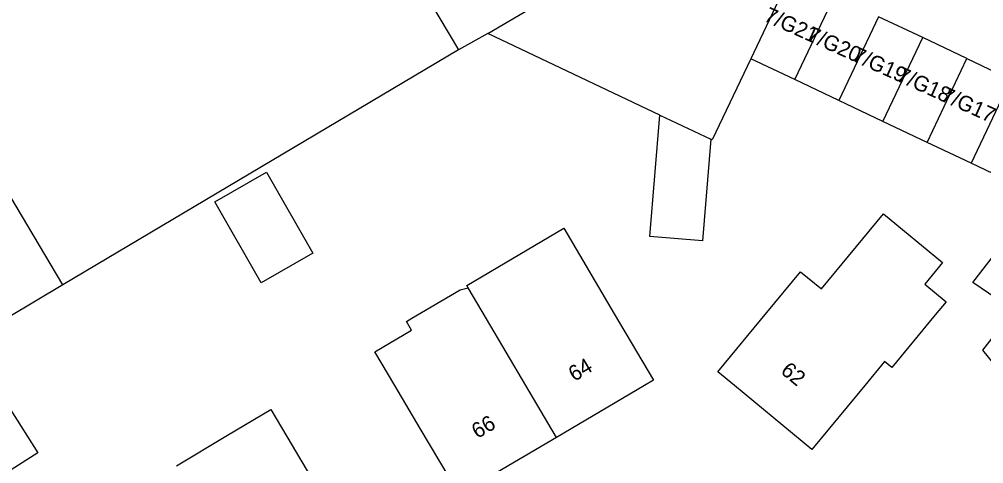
# Model space of a CAD drawing. Extents: x 159503 to 160347, y 382525 to 383272.
# Drawn here: x 159688.9 to 159751.6, y 382994.9 to 383023.8 of the extents above; entities that cross this region are included whole.
import ezdxf

# ---------------------------------------------------------------- set-up
doc = ezdxf.new("R2010")
doc.units = 0
doc.layers.add('IMGEO_Pand', color=7, linetype='Continuous')
doc.layers.add('IMGEO_Pand_nummerreeks', color=7, linetype='Continuous')

msp = doc.modelspace()

# ---------------------------------------------------------------- linework, layer by layer
at = {"layer": 'IMGEO_Pand'}
for points in [[(159707.235, 383039.014), (159717.447, 383021.814)], [(159719.37, 383022.877), (159727.798, 383027.878)], [(159739.021, 383026.698), (159736.443, 383021.244)], [(159739.304, 383019.887), (159741.889, 383025.338)], [(159691.726, 383006.538), (159681.512, 383023.741)], [(159744.757, 383023.978), (159742.172, 383018.527)], [(159747.624, 383022.618), (159744.757, 383023.978)], [(159719.37, 383022.877), (159717.447, 383021.814)], [(159730.549, 383017.575), (159719.37, 383022.877)], [(159745.039, 383017.167), (159747.624, 383022.618)], [(159750.492, 383021.257), (159747.624, 383022.618)], [(159717.447, 383021.814), (159691.726, 383006.538)], [(159736.443, 383021.244), (159733.94, 383015.967), (159733.862, 383016.004)], [(159739.304, 383019.887), (159736.443, 383021.244)], [(159747.907, 383015.807), (159750.492, 383021.257)], [(159750.492, 383021.257), (159753.36, 383019.897)], [(159742.172, 383018.527), (159739.304, 383019.887)], [(159753.36, 383019.897), (159750.775, 383014.446)], [(159745.039, 383017.167), (159742.172, 383018.527)], [(159733.862, 383016.004), (159733.304, 383009.403), (159729.882, 383009.693), (159730.549, 383017.575)], [(159730.549, 383017.575), (159733.862, 383016.004)], [(159747.907, 383015.807), (159745.039, 383017.167)], [(159750.775, 383014.446), (159747.907, 383015.807)], [(159753.643, 383013.086), (159750.775, 383014.446)], [(159707.992, 383008.609), (159704.632, 383006.683), (159701.62, 383011.936), (159704.98, 383013.863), (159707.992, 383008.609)], [(159758.283, 383010.865), (159753.467, 383004.946), (159750.876, 383006.697), (159755.183, 383012.265), (159758.283, 383010.865)], [(159748.919, 383007.996), (159747.755, 383006.585), (159749.142, 383005.441), (159748.44, 383004.59), (159745.617, 383001.169), (159745.143, 383001.56), (159743.853, 383000), (159740.42, 382995.85), (159735.39, 383000), (159734.311, 383000.89), (159737.493, 383004.747), (159739.679, 383007.397), (159741.037, 383006.277), (159745.073, 383011.167), (159748.919, 383007.996)], [(159718.079, 383006.352), (159717.995, 383006.494), (159721.45, 383008.543), (159724.297, 383010.231), (159727.581, 383004.651), (159730.118, 383000.341), (159729.54, 383000), (159723.819, 382996.623)], [(159691.726, 383006.538), (159684.709, 383002.371)], [(159723.819, 382996.623), (159717.522, 382992.906), (159714.972, 382997.208), (159713.315, 383000), (159712.015, 383002.191), (159714.397, 383003.603), (159714.066, 383004.161), (159714.428, 383004.375), (159717.552, 383006.226), (159718.079, 383006.352)], [(159723.819, 382996.623), (159721.827, 383000), (159719.266, 383004.34), (159718.079, 383006.352)], [(159759.987, 382998.579), (159756.7, 382995.911), (159751.525, 383002.289), (159754.195, 383005.716)], [(159684.01, 382998.362), (159683.51, 382999.204), (159686.583, 383001.161), (159690.111, 382995.622), (159686.864, 382993.555)], [(159699.135, 382994.785), (159702.448, 382996.78), (159705.257, 382998.445), (159707.969, 382993.869), (159710.519, 382989.567), (159709.083, 382988.716), (159709.442, 382988.11), (159705.787, 382985.943), (159705.426, 382986.552), (159704.379, 382985.932)]]:
    msp.add_lwpolyline(points, dxfattribs=at)

# ---------------------------------------------------------------- texts
at = {"layer": 'IMGEO_Pand_nummerreeks'}
for s, rotation, p in [('7/G21', 335.75407, (159737.235, 383023.725)), ('7/G20', 335.75407, (159740.015, 383022.473)), ('7/G19', 335.75407, (159742.971, 383021.141)), ('7/G18', 335.75407, (159745.855, 383019.843)), ('7/G17', 335.75407, (159748.73, 383018.548)), ('64', 30.55011, (159724.975, 383000.232)), ('62', 320.47695, (159738.33, 383000.843)), ('66', 30.55011, (159718.678, 382996.515))]:
    msp.add_text(s, height=1, rotation=rotation, dxfattribs=at).set_placement(p)

doc.saveas('drawing.dxf')
